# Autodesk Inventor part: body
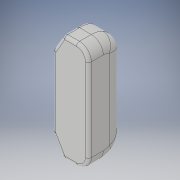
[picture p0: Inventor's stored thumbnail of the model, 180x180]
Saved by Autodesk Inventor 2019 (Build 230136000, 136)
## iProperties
Created: 2020-08
Part Number: body
Material: 一般
Document SubType Name: Modeling
Designer: kikut
Density: 1 g/cm^3
Appearance: 既定
Author: kikut
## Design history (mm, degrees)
sketch "スケッチ1"
  geometry: L1 (-0.06, -0.18)-(0.06, -0.18); L2 (0.06, -0.18)-(0.06, 0.18); L3 (0.06, 0.18)-(-0.06, 0.18); L4 (-0.06, 0.18)-(-0.06, -0.18); L5 (-0.06, -0.18)-(0.06, 0.18); L6 (0.06, -0.18)-(-0.06, 0.18); 1 further point
  constraints: 12 end point, 2 midpoint, 2 parallel, 1 horizontal, 1 perpendicular
  dimensions: "d0" = 0.36 distance of L1.end L2.end; "d1" = 0.12 distance of L2.end L3.end
extrude "押し出し1" new body sketch "スケッチ1" distance "d2" = 0.06; taper "d4" = 0 deg; dims "d3" = 0.07, "d5" = 0
fillet "フィレット2" dims "d7" = 0.08
sketch "スケッチ2"
  geometry: L1 (0.12, -0.05)-(0.12, -0.13) reference; L2 (0.12, -0.07)-(0.14, -0.07); L3 (0.14, -0.07)-(0.14, -0.17); L4 (0.14, -0.17)-(-0.02, -0.17); L5 (-0.02, -0.17)-(-0.02, -0.07); L6 (-0.02, -0.07)-(0, -0.07); L7 (0, 0)-(0.12, 0) reference; A1 r 0.06 centre (0.06, -0.07) between (0, -0.07) and (0.12, -0.07); 1 further point
  constraints: 10 end point, 4 perpendicular, 2 point on circle, 2 point on line, 1 centre point, 1 horizontal
  dimensions: "d8" = 0.06 radius of A1; "d9" = 0.02 distance of L5.end L6.end; "d10" = 0.02 distance of L2.start L2.end; "d11" = 0.16 distance of L3.end L4.end; "d12" = 0.1 distance of L2.end L3.end; "d13" = 0.13 dimension on A1 L7
extrude "押し出し2" cut sketch "スケッチ2" extent not by distance; stored distance "d14" = 0.06; taper "d15" = 0 deg
sketch "スケッチ3"
  geometry: L1 (-0.06, 0.2)-(-0.014, 0.2); L2 (-0.014, 0.2)-(-0.06, 0.12); L3 (-0.06, 0.12)-(-0.06, 0.2); L4 (-0.2, 0)-(0.104, 0) reference; L5 (0, -0.256)-(0, 0.278) reference; L6 (-0.06, -0.12)-(-0.06, -0.2); L7 (-0.06, -0.2)-(-0.014, -0.2); L8 (-0.014, -0.2)-(-0.06, -0.12); 1 further point
  constraints: 12 end point, 2 perpendicular, 1 horizontal, 1 vertical
  dimensions: "d18" = 60 deg angle of L2 L4; "d19" = 0.06 distance between parallel lines of L5 L3; "d21" = 0.12 distance from line of L2.end L4; "d22" = 0.08 distance of L2.end L1.start; "d23" = 30 deg angle of L8 L6; "d24" = 0.12 distance from line of L6.start L4; "d25" = 0.08 distance of L6.start L6.end; "d26" = 0.06 distance between parallel lines of L5 L6
extrude "押し出し3" cut sketch "スケッチ3" distance "d27" = 10; taper "d28" = 0 deg
fillet "フィレット6" dims "d30" = 0.04
fillet "フィレット7" dims "d31" = 0.01
node "ソリッド1"
